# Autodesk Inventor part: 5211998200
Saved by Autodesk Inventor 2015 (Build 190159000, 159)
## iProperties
Created: 2020-07
Part Number: 5211998200
Checked By: TraceParts S.A.
Material: Generic
Catalog Web Link: www.traceparts.com
Document SubType Name: Modeling
Designer: TraceParts
Density: 1 g/cm^3
Appearance: Default
Company: TraceParts S.A.
Author: TraceParts
REFERENCE: 5211998200
DESIGN: TDM-200 (220V 60) BRA RZ - 5211998200
SUPPLIER: Soler & Palau
TraceParts.PartNumber: 10-20122018-119657
TraceParts.PartTitle: TDM
TraceParts.InstanceId: 10-20122018-119657CDNU9JYU3RW0MQ57GH6E2GVIH
TraceParts.PartStatus: Published
TraceParts.PartVersion: 1.0.2
TRACEPARTS: TRACEPARTS
TraceParts.PartLanguage: en
TraceParts.ClassPath: SOLER_PALAU:10-20122018-119657
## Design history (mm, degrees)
feature "5211998200"
body "Solid1"
